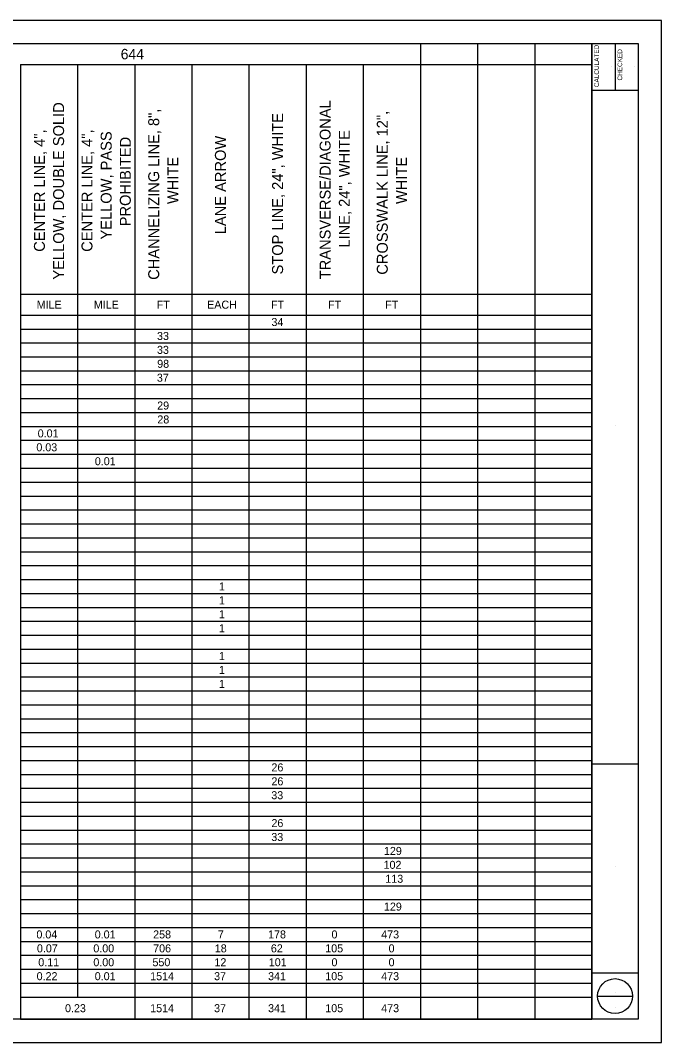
# Model space of a CAD drawing. Extents: x 10.3 to 44.3, y 3.4 to 25.4.
# Drawn here: x 30.51 to 44.31, y 3.4 to 25.4 of the extents above; entities that cross this region are included whole.
import ezdxf

# ---------------------------------------------------------------- set-up
doc = ezdxf.new("R2010")
doc.units = 0
for name, color, linetype in [('SH_Border', 7, 'Continuous'), ('SH_Cut_Line', 7, 'Continuous'), ('SH_Data', 7, 'Continuous'), ('SH_Text', 7, 'Continuous')]:
    doc.layers.add(name, color=color, linetype=linetype)

msp = doc.modelspace()

# ---------------------------------------------------------------- linework, layer by layer
at = {"layer": 'SH_Border'}
for p, q in [((42.806, 3.905), (42.806, 24.905)), ((43.306, 24.905), (43.306, 23.905)), ((42.806, 23.905), (43.806, 23.905)), ((42.806, 9.405), (43.806, 9.405)), ((42.806, 4.905), (43.806, 4.905))]:
    msp.add_line(p, q, dxfattribs=at)
msp.add_lwpolyline([(12.306, 24.905), (43.806, 24.905), (43.806, 3.905), (12.306, 3.905)], close=True, dxfattribs=at)
at = {"layer": 'SH_Cut_Line'}
msp.add_lwpolyline([(10.306, 3.405), (44.306, 3.405), (44.306, 25.405), (10.306, 25.405)], close=True, dxfattribs=at)
at = {"layer": 'SH_Data'}
for p, q in [((43.226, 24.408), (43.226, 24.408)), ((43.726, 24.408), (43.726, 24.408)), ((43.306, 16.696), (43.306, 16.696)), ((43.306, 7.196), (43.306, 7.196)), ((42.931, 4.405), (43.681, 4.405)), ((43.306, 4.49), (43.306, 4.49)), ((43.306, 4.15), (43.306, 4.15))]:
    msp.add_line(p, q, dxfattribs=at)
msp.add_circle((43.306, 4.405), 0.375, dxfattribs=at)
at = {"layer": 'SH_Text'}
for p, q in [((30.512, 24.905), (34.2, 24.905)), ((34.2, 24.905), (36.659, 24.905)), ((36.659, 24.905), (41.577, 24.905)), ((39.118, 24.905), (39.118, 12.173)), ((40.347, 24.905), (40.347, 12.173)), ((41.577, 24.905), (42.806, 24.905)), ((41.577, 24.905), (41.577, 12.173)), ((42.806, 24.905), (42.806, 12.173)), ((30.512, 24.455), (34.2, 24.455)), ((30.512, 24.455), (30.512, 12.173)), ((31.741, 24.455), (31.741, 12.173)), ((32.97, 24.455), (32.97, 12.173)), ((34.2, 24.455), (36.659, 24.455)), ((34.2, 24.455), (34.2, 12.173)), ((35.429, 24.455), (35.429, 12.173)), ((36.659, 24.455), (41.577, 24.455)), ((36.659, 24.455), (36.659, 12.173)), ((37.888, 24.455), (37.888, 12.173)), ((41.577, 24.455), (42.806, 24.455)), ((30.512, 19.512), (34.2, 19.512)), ((34.2, 19.512), (36.659, 19.512)), ((36.659, 19.512), (41.577, 19.512)), ((41.577, 19.512), (42.806, 19.512)), ((30.512, 19.063), (34.2, 19.063)), ((34.2, 19.063), (36.659, 19.063)), ((36.659, 19.063), (41.577, 19.063)), ((41.577, 19.063), (42.806, 19.063)), ((30.512, 18.763), (34.2, 18.763)), ((34.2, 18.763), (36.659, 18.763)), ((36.659, 18.763), (41.577, 18.763)), ((41.577, 18.763), (42.806, 18.763)), ((30.512, 18.464), (34.2, 18.464)), ((34.2, 18.464), (36.659, 18.464)), ((36.659, 18.464), (41.577, 18.464)), ((41.577, 18.464), (42.806, 18.464)), ((30.512, 18.164), (34.2, 18.164)), ((34.2, 18.164), (36.659, 18.164)), ((36.659, 18.164), (41.577, 18.164)), ((41.577, 18.164), (42.806, 18.164)), ((30.512, 17.865), (34.2, 17.865)), ((34.2, 17.865), (36.659, 17.865)), ((36.659, 17.865), (41.577, 17.865)), ((41.577, 17.865), (42.806, 17.865)), ((30.512, 17.565), (34.2, 17.565)), ((34.2, 17.565), (36.659, 17.565)), ((36.659, 17.565), (41.577, 17.565)), ((41.577, 17.565), (42.806, 17.565)), ((30.512, 17.265), (34.2, 17.265)), ((34.2, 17.265), (36.659, 17.265)), ((36.659, 17.265), (41.577, 17.265)), ((41.577, 17.265), (42.806, 17.265)), ((30.512, 16.966), (34.2, 16.966)), ((34.2, 16.966), (36.659, 16.966)), ((36.659, 16.966), (41.577, 16.966)), ((41.577, 16.966), (42.806, 16.966)), ((30.512, 16.666), (34.2, 16.666)), ((34.2, 16.666), (36.659, 16.666)), ((36.659, 16.666), (41.577, 16.666)), ((41.577, 16.666), (42.806, 16.666)), ((30.512, 16.367), (34.2, 16.367)), ((34.2, 16.367), (36.659, 16.367)), ((36.659, 16.367), (41.577, 16.367)), ((41.577, 16.367), (42.806, 16.367)), ((30.512, 16.067), (34.2, 16.067)), ((34.2, 16.067), (36.659, 16.067)), ((36.659, 16.067), (41.577, 16.067)), ((41.577, 16.067), (42.806, 16.067)), ((30.512, 15.768), (34.2, 15.768)), ((34.2, 15.768), (36.659, 15.768)), ((36.659, 15.768), (41.577, 15.768)), ((41.577, 15.768), (42.806, 15.768)), ((30.512, 15.468), (34.2, 15.468)), ((34.2, 15.468), (36.659, 15.468)), ((36.659, 15.468), (41.577, 15.468)), ((41.577, 15.468), (42.806, 15.468)), ((30.512, 15.168), (34.2, 15.168)), ((34.2, 15.168), (36.659, 15.168)), ((36.659, 15.168), (41.577, 15.168)), ((41.577, 15.168), (42.806, 15.168)), ((30.512, 14.869), (34.2, 14.869)), ((34.2, 14.869), (36.659, 14.869)), ((36.659, 14.869), (41.577, 14.869)), ((41.577, 14.869), (42.806, 14.869)), ((30.512, 14.569), (34.2, 14.569)), ((34.2, 14.569), (36.659, 14.569)), ((36.659, 14.569), (41.577, 14.569)), ((41.577, 14.569), (42.806, 14.569)), ((30.512, 14.27), (34.2, 14.27)), ((34.2, 14.27), (36.659, 14.27)), ((36.659, 14.27), (41.577, 14.27)), ((41.577, 14.27), (42.806, 14.27)), ((30.512, 13.97), (34.2, 13.97)), ((34.2, 13.97), (36.659, 13.97)), ((36.659, 13.97), (41.577, 13.97)), ((41.577, 13.97), (42.806, 13.97)), ((30.512, 13.671), (34.2, 13.671)), ((34.2, 13.671), (36.659, 13.671)), ((36.659, 13.671), (41.577, 13.671)), ((41.577, 13.671), (42.806, 13.671)), ((30.512, 13.371), (34.2, 13.371)), ((34.2, 13.371), (36.659, 13.371)), ((36.659, 13.371), (41.577, 13.371)), ((41.577, 13.371), (42.806, 13.371)), ((30.512, 13.071), (34.2, 13.071)), ((34.2, 13.071), (36.659, 13.071)), ((36.659, 13.071), (41.577, 13.071)), ((41.577, 13.071), (42.806, 13.071)), ((30.512, 12.772), (34.2, 12.772)), ((34.2, 12.772), (36.659, 12.772)), ((36.659, 12.772), (41.577, 12.772)), ((41.577, 12.772), (42.806, 12.772)), ((30.512, 12.472), (34.2, 12.472)), ((34.2, 12.472), (36.659, 12.472)), ((36.659, 12.472), (41.577, 12.472)), ((41.577, 12.472), (42.806, 12.472)), ((30.512, 12.173), (34.2, 12.173)), ((30.512, 12.173), (30.512, 3.905)), ((31.741, 12.173), (31.741, 4.384)), ((32.97, 12.173), (32.97, 3.905)), ((34.2, 12.173), (36.659, 12.173)), ((34.2, 12.173), (34.2, 3.905)), ((35.429, 12.173), (35.429, 3.905)), ((36.659, 12.173), (41.577, 12.173)), ((36.659, 12.173), (36.659, 3.905)), ((37.888, 12.173), (37.888, 3.905)), ((39.118, 12.173), (39.118, 3.905)), ((40.347, 12.173), (40.347, 3.905)), ((41.577, 12.173), (42.806, 12.173)), ((41.577, 12.173), (41.577, 3.905)), ((42.806, 12.173), (42.806, 3.905)), ((30.512, 11.873), (34.2, 11.873)), ((34.2, 11.873), (36.659, 11.873)), ((36.659, 11.873), (41.577, 11.873)), ((41.577, 11.873), (42.806, 11.873)), ((30.512, 11.574), (34.2, 11.574)), ((34.2, 11.574), (36.659, 11.574)), ((36.659, 11.574), (41.577, 11.574)), ((41.577, 11.574), (42.806, 11.574)), ((30.512, 11.274), (34.2, 11.274)), ((34.2, 11.274), (36.659, 11.274)), ((36.659, 11.274), (41.577, 11.274)), ((41.577, 11.274), (42.806, 11.274)), ((30.512, 10.974), (34.2, 10.974)), ((34.2, 10.974), (36.659, 10.974)), ((36.659, 10.974), (41.577, 10.974)), ((41.577, 10.974), (42.806, 10.974)), ((30.512, 10.675), (34.2, 10.675)), ((34.2, 10.675), (36.659, 10.675)), ((36.659, 10.675), (41.577, 10.675)), ((41.577, 10.675), (42.806, 10.675)), ((30.512, 10.375), (34.2, 10.375)), ((34.2, 10.375), (36.659, 10.375)), ((36.659, 10.375), (41.577, 10.375)), ((41.577, 10.375), (42.806, 10.375)), ((30.512, 10.076), (34.2, 10.076)), ((34.2, 10.076), (36.659, 10.076)), ((36.659, 10.076), (41.577, 10.076)), ((41.577, 10.076), (42.806, 10.076)), ((30.512, 9.776), (34.2, 9.776)), ((34.2, 9.776), (36.659, 9.776)), ((36.659, 9.776), (41.577, 9.776)), ((41.577, 9.776), (42.806, 9.776)), ((30.512, 9.477), (34.2, 9.477)), ((34.2, 9.477), (36.659, 9.477)), ((36.659, 9.477), (41.577, 9.477)), ((41.577, 9.477), (42.806, 9.477)), ((30.512, 9.177), (34.2, 9.177)), ((34.2, 9.177), (36.659, 9.177)), ((36.659, 9.177), (41.577, 9.177)), ((41.577, 9.177), (42.806, 9.177)), ((30.512, 8.877), (34.2, 8.877)), ((34.2, 8.877), (36.659, 8.877)), ((36.659, 8.877), (41.577, 8.877)), ((41.577, 8.877), (42.806, 8.877)), ((30.512, 8.578), (34.2, 8.578)), ((34.2, 8.578), (36.659, 8.578)), ((36.659, 8.578), (41.577, 8.578)), ((41.577, 8.578), (42.806, 8.578)), ((30.512, 8.278), (34.2, 8.278)), ((34.2, 8.278), (36.659, 8.278)), ((36.659, 8.278), (41.577, 8.278)), ((41.577, 8.278), (42.806, 8.278)), ((30.512, 7.979), (34.2, 7.979)), ((34.2, 7.979), (36.659, 7.979)), ((36.659, 7.979), (41.577, 7.979)), ((41.577, 7.979), (42.806, 7.979)), ((30.512, 7.679), (34.2, 7.679)), ((34.2, 7.679), (36.659, 7.679)), ((36.659, 7.679), (41.577, 7.679)), ((41.577, 7.679), (42.806, 7.679)), ((30.512, 7.38), (34.2, 7.38)), ((34.2, 7.38), (36.659, 7.38)), ((36.659, 7.38), (41.577, 7.38)), ((41.577, 7.38), (42.806, 7.38)), ((30.512, 7.08), (34.2, 7.08)), ((34.2, 7.08), (36.659, 7.08)), ((36.659, 7.08), (41.577, 7.08)), ((41.577, 7.08), (42.806, 7.08)), ((30.512, 6.78), (34.2, 6.78)), ((34.2, 6.78), (36.659, 6.78)), ((36.659, 6.78), (41.577, 6.78)), ((41.577, 6.78), (42.806, 6.78)), ((30.512, 6.481), (34.2, 6.481)), ((34.2, 6.481), (36.659, 6.481)), ((36.659, 6.481), (41.577, 6.481)), ((41.577, 6.481), (42.806, 6.481)), ((30.512, 6.181), (34.2, 6.181)), ((34.2, 6.181), (36.659, 6.181)), ((36.659, 6.181), (41.577, 6.181)), ((41.577, 6.181), (42.806, 6.181)), ((30.512, 5.882), (34.2, 5.882)), ((34.2, 5.882), (36.659, 5.882)), ((36.659, 5.882), (41.577, 5.882)), ((41.577, 5.882), (42.806, 5.882)), ((30.512, 5.582), (34.2, 5.582)), ((34.2, 5.582), (36.659, 5.582)), ((36.659, 5.582), (41.577, 5.582)), ((41.577, 5.582), (42.806, 5.582)), ((30.512, 5.283), (34.2, 5.283)), ((34.2, 5.283), (36.659, 5.283)), ((36.659, 5.283), (41.577, 5.283)), ((41.577, 5.283), (42.806, 5.283)), ((30.512, 4.983), (34.2, 4.983)), ((34.2, 4.983), (36.659, 4.983)), ((36.659, 4.983), (41.577, 4.983)), ((41.577, 4.983), (42.806, 4.983)), ((30.512, 4.683), (34.2, 4.683)), ((34.2, 4.683), (36.659, 4.683)), ((36.659, 4.683), (41.577, 4.683)), ((41.577, 4.683), (42.806, 4.683)), ((30.512, 4.384), (34.2, 4.384)), ((34.2, 4.384), (36.659, 4.384)), ((36.659, 4.384), (41.577, 4.384)), ((41.577, 4.384), (42.806, 4.384)), ((30.512, 3.905), (34.2, 3.905)), ((34.2, 3.905), (36.659, 3.905)), ((36.659, 3.905), (41.577, 3.905)), ((41.577, 3.905), (42.806, 3.905))]:
    msp.add_line(p, q, dxfattribs=at)

# ---------------------------------------------------------------- texts
at = {"layer": 'SH_Data'}
for s, p in [('CALCULATED', (42.959, 23.969)), ('CHECKED', (43.459, 24.112))]:
    msp.add_text(s, height=0.1, rotation=90, dxfattribs=at).set_placement(p)
at = {"layer": 'SH_Text'}
for s, height, p in [('644', 0.2239, (32.669, 24.568)), ('MILE', 0.1723, (30.861, 19.201)), ('MILE', 0.1723, (32.09, 19.201)), ('FT', 0.1723, (33.443, 19.201)), ('EACH', 0.1723, (34.528, 19.201)), ('FT', 0.1723, (35.902, 19.201)), ('FT', 0.1723, (37.131, 19.201)), ('FT', 0.1723, (38.36, 19.201)), ('34', 0.1723, (35.912, 18.827)), ('33', 0.1723, (33.45, 18.527)), ('33', 0.1723, (33.45, 18.228)), ('98', 0.1723, (33.454, 17.928)), ('37', 0.1723, (33.447, 17.629)), ('29', 0.1723, (33.454, 17.03)), ('28', 0.1723, (33.457, 16.73)), ('0.01', 0.1723, (30.883, 16.43)), ('0.03', 0.1723, (30.854, 16.131)), ('0.01', 0.1723, (32.112, 15.831)), ('1', 0.172, (34.781, 13.135)), ('1', 0.172, (34.781, 12.836)), ('1', 0.172, (34.781, 12.536)), ('1', 0.172, (34.781, 12.236)), ('1', 0.172, (34.781, 11.637)), ('1', 0.172, (34.781, 11.338)), ('1', 0.172, (34.781, 11.038)), ('26', 0.1723, (35.912, 9.241)), ('26', 0.1723, (35.912, 8.941)), ('33', 0.1723, (35.909, 8.642)), ('26', 0.1723, (35.912, 8.042)), ('33', 0.1723, (35.909, 7.743)), ('129', 0.1723, (38.333, 7.443)), ('102', 0.1723, (38.325, 7.144)), ('113', 0.1723, (38.363, 6.844)), ('129', 0.1723, (38.333, 6.245)), ('0.04', 0.1723, (30.855, 5.646)), ('0.01', 0.1723, (32.11, 5.646)), ('258', 0.1723, (33.367, 5.646)), ('7', 0.172, (34.76, 5.646)), ('178', 0.1723, (35.84, 5.646)), ('0', 0.172, (37.204, 5.646)), ('473', 0.1723, (38.274, 5.646)), ('0.07', 0.1723, (30.866, 5.346)), ('0.00', 0.1723, (32.08, 5.346)), ('706', 0.1723, (33.367, 5.346)), ('18', 0.1723, (34.693, 5.346)), ('62', 0.1723, (35.9, 5.346)), ('105', 0.1723, (37.07, 5.346)), ('0', 0.172, (38.433, 5.346)), ('0.11', 0.1723, (30.895, 5.047)), ('0.00', 0.1723, (32.08, 5.047)), ('550', 0.1723, (33.352, 5.047)), ('12', 0.1723, (34.686, 5.047)), ('101', 0.1723, (35.855, 5.047)), ('0', 0.172, (37.204, 5.047)), ('0', 0.172, (38.433, 5.047)), ('0.22', 0.1723, (30.86, 4.747)), ('0.01', 0.1723, (32.11, 4.747)), ('1514', 0.1723, (33.303, 4.747)), ('37', 0.1723, (34.678, 4.747)), ('341', 0.1723, (35.84, 4.747)), ('105', 0.1723, (37.07, 4.747)), ('473', 0.1723, (38.274, 4.747)), ('0.23', 0.1723, (31.471, 4.058)), ('1514', 0.1723, (33.303, 4.058)), ('37', 0.1723, (34.678, 4.058)), ('341', 0.1723, (35.84, 4.058)), ('105', 0.1723, (37.07, 4.058)), ('473', 0.1723, (38.274, 4.058))]:
    msp.add_text(s, height=height, dxfattribs=at).set_placement(p)
for s, height, p in [('YELLOW, DOUBLE SOLID', 0.23565, (31.45, 19.826)), ('TRANSVERSE/DIAGONAL', 0.23565, (37.185, 19.834)), ('CHANNELIZING LINE, 8",', 0.23565, (33.497, 19.822)), ('STOP LINE, 24", WHITE', 0.23565, (36.162, 19.937)), ('CROSSWALK LINE, 12",', 0.23565, (38.415, 19.932)), ('CENTER LINE, 4",', 0.23565, (31.038, 20.425)), ('CENTER LINE, 4",', 0.23565, (32.061, 20.425)), ('YELLOW, PASS', 0.23565, (32.474, 20.689)), ('PROHIBITED', 0.2356, (32.886, 20.974)), ('LANE ARROW', 0.2356, (34.932, 20.804)), ('LINE, 24", WHITE', 0.23565, (37.598, 20.516)), ('WHITE', 0.2356, (33.909, 21.453)), ('WHITE', 0.2356, (38.827, 21.453))]:
    msp.add_text(s, height=height, rotation=90, dxfattribs=at).set_placement(p)

doc.saveas('drawing.dxf')
